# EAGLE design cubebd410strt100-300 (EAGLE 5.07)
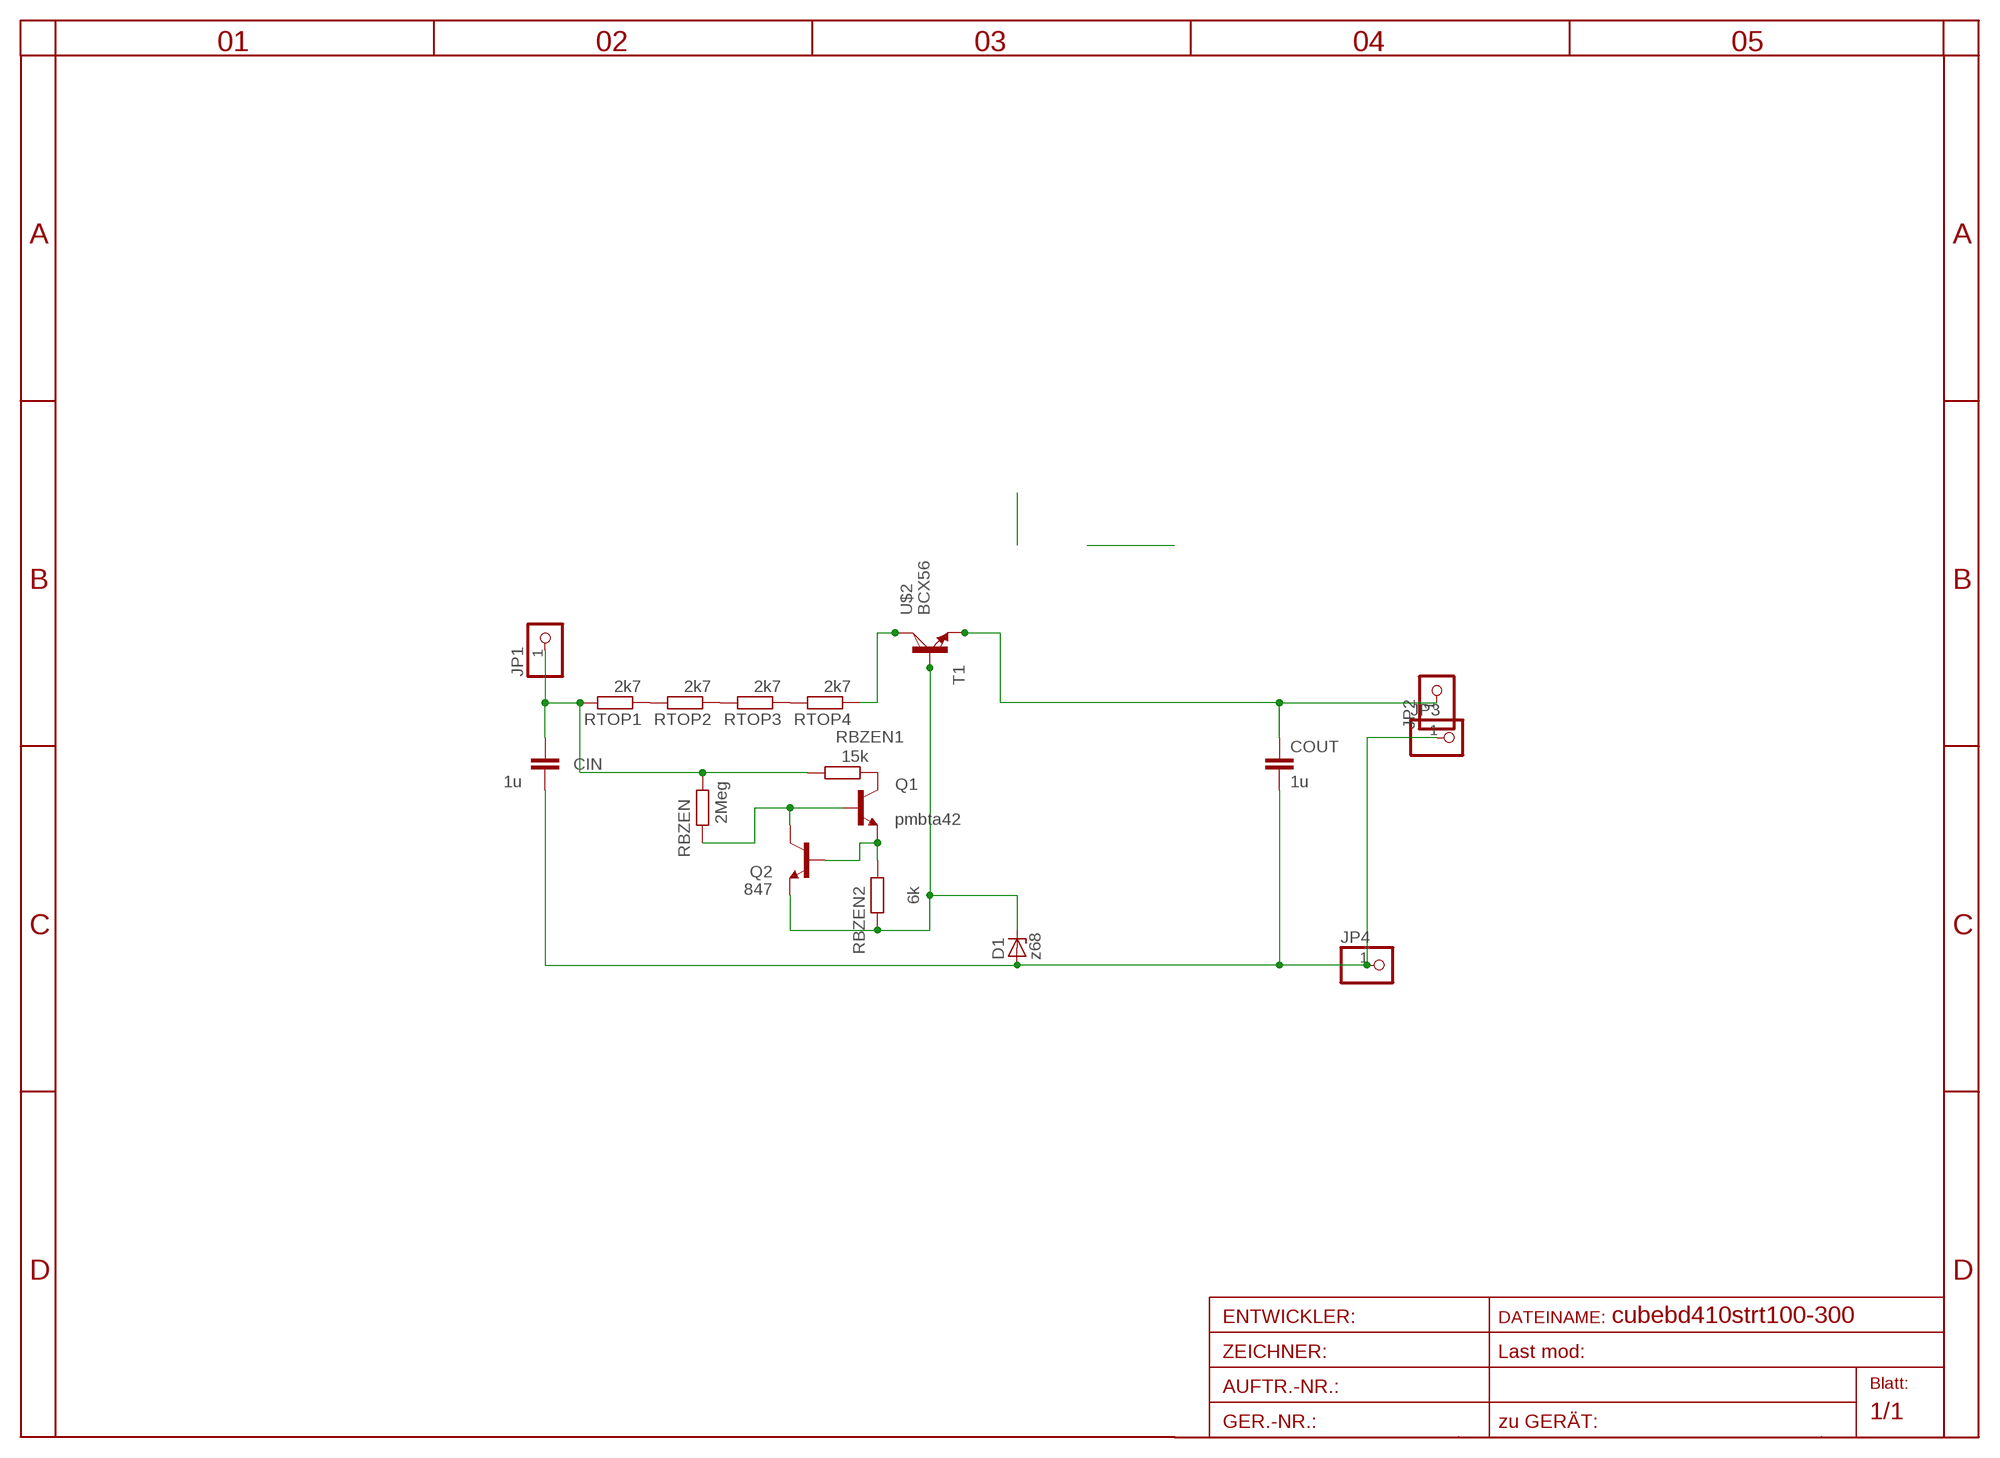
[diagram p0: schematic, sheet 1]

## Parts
CIN  1u  C-EU025-024X044  [C025-024X044]
COUT  1u  C-EU025_050-055X075  [C025_050-055X075]
D1  z68  ZENER-DIODESOD80C  [SOD80C]
JP1  PINHD-1X11X0.4  [1X01]
JP2  PINHD-1X11X0.4  [1X01]
JP3  PINHD-1X11X0.4  [1X01]
JP4  PINHD-1X11X0.4  [1X01]
Q1  pmbta42  BC847ASMD  [SOT23]
Q2  847  BC847ASMD  [SOT23]
RBZEN  2Meg  R-EU_0207/7  [0207/7]
RBZEN1  15k  R-EU_0207/7  [0207/7]
RBZEN2  6k  R-EU_0204/7  [0204/7]
RTOP1  2k7  R-EU_0204/2V  [0204V]
RTOP2  2k7  R-EU_0204/2V  [0204V]
RTOP3  2k7  R-EU_0204/2V  [0204V]
RTOP4  2k7  R-EU_0204/5  [0204/5]
T1  -NPN-TO126V  [TO126V]
U$2  BCX56  [SOT223]

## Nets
C: RTOP4.1 T1.2(C) U$2.2(C)
CB: Q1.1(B) Q2.3(C) RBZEN.2
DB: D1.C Q2.2(E) RBZEN2.2 T1.3(B) U$2.1(B)
EB: Q1.2(E) Q2.1(B) RBZEN2.1
GND: CIN.2 COUT.2 D1.A JP3.1 JP4.1
N$1: Q1.3(C) RBZEN1.1
N$2: RTOP1.1 RTOP2.2
N$7: RTOP2.1 RTOP3.2
N$8: RTOP3.1 RTOP4.2
OUT: COUT.1 JP2.1 T1.1(E) U$2.3(E)
VPLUS: CIN.1 JP1.1 RBZEN1.2 RBZEN.1 RTOP1.2

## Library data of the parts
CIN COUT = rcl:C-EU: CAPACITOR, European symbol
D1 = diode:ZENER-DIODE: Z-Diode
JP1-JP4 = pinhead:PINHD-1X1: PIN HEADER
Q1 Q2 = transistor-npn:BC847*: NPN Transistor
RBZEN RBZEN1 RBZEN2 RTOP1-RTOP4 = rcl:R-EU_: RESISTOR, European symbol
T1 = transistor:*-NPN-: NPN Transistror BF959 corrected 2008.03.06
U$2 = transistor-power:BCX56

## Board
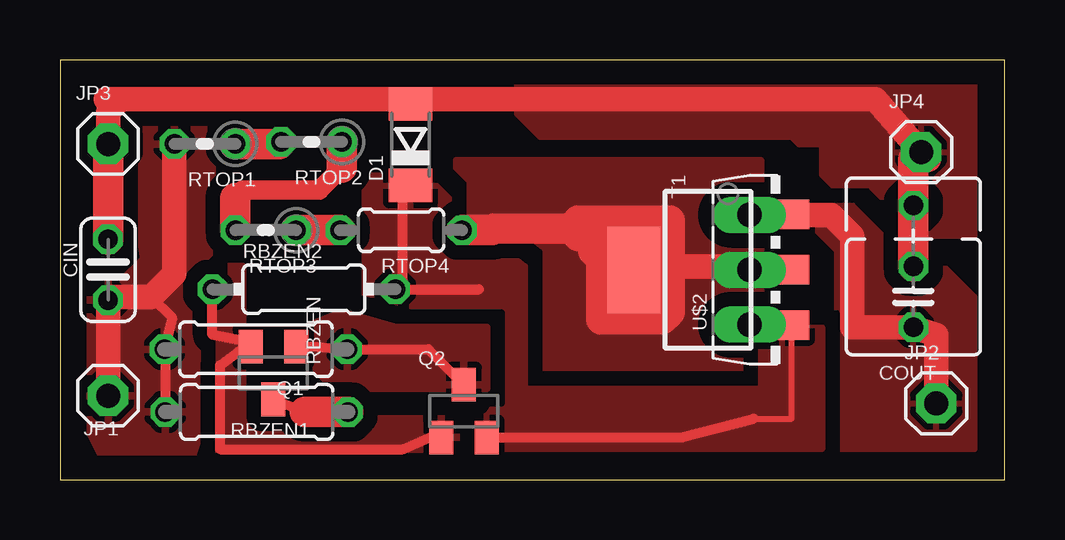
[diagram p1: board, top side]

Size 39.37 x 17.5 mm. Coordinates in mm from the lower left corner, seen from the top.
Outline: 0,0 39.37,0 39.37,17.5 0,17.5 0,0
Copper layers (1*16): Top 0.035mm / dielectric 1.5mm / Bottom 0.035mm
Design rules "default *": minimum track width 10mil, minimum drill 20mil, track to track 8mil, track to pad 8mil, pad to pad 8mil, via to via 8mil, smd to smd 8mil, copper to edge 40mil, drill to drill 8mil, minimum pad ring 1mil, minimum via ring 8mil, stop-mask expansion 4mil, vias tented up to drill 0mil, thermal gap 10mil

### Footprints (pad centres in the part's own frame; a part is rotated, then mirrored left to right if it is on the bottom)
C025-024X044 = drill 0.813 octagon: 1 -1.27,0; 2 1.27,0
C025_050-055X075 = drill 0.813 octagon: 1 -1.27,0; 2 1.27,0; 3 3.81,0
SOD80C = smd 1.4 x 1.8: A 1.7,0; C -1.7,0
1X01 = drill 1 pad 1.676 octagon: 1 0,0
SOT23 = smd 1 x 1.4: 1 -0.95,-1.1; 2 0.95,-1.1; 3 0,1.1
0207/7 = drill 0.813 octagon: 1 -3.81,0; 2 3.81,0
0204/7 = drill 0.813 octagon: 1 -3.81,0; 2 3.81,0
0204V = drill 0.813 octagon: 1 -1.27,0; 2 1.27,0
0204/5 = drill 0.813 octagon: 1 -2.54,0; 2 2.54,0
TO126V = drill 1.016 long: 1 -2.286,-1.27; 2 0,-1.27; 3 2.286,-1.27
SOT223 = smd 1.219 x 2.235: 1 -2.311,-3.099; 2 0,-3.099; 3 2.311,-3.099 | smd 3.6 x 2.2: 4 0,3.099

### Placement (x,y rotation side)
CIN  2,8.75 90 top
COUT  35.56,7.62 90 top
D1  14.61,13.97 90 top
JP1  2,3.5 0 top
JP2  36.51,3.17 0 top
JP3  2,14 0 top
JP4  35.88,13.65 0 top
Q1  8.89,4.45 180 top
Q2  16.83,2.86 0 top
RBZEN  8.16,5.44 0 top
RBZEN1  8.2,2.82 180 top
RBZEN2  10.16,7.94 0 top
RTOP1  6.03,14 180 top
RTOP2  10.48,14.08 180 top
RTOP3  8.57,10.4 180 top
RTOP4  14.21,10.4 180 top
T1  30,8.75 270 top
U$2  27,8.75 90 top

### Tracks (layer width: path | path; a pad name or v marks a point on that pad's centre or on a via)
C
  Top 0.305: 18.02,10.4 18.1,10.48
  Top 0.406: 27.68,8.89 T1.2
  Top 1.016: 20.95,10.48 25.4,8.89 27.68,8.89 | T1.2 U$2.2
  Top 1.27: 18.1,10.48 20.95,10.48 | RTOP4.1 18.02,10.4 | 21.59,10.16 21.59,10.79 25.4,10.79 25.4,6.99 25.08,6.67 22.54,6.67 22.54,9.21 22.23,9.53
  pour Top (isolate 0.61, rank 3, no thermals): 16.51,13.34 29.21,13.34 29.21,3.81 19.05,3.81 19.05,8.89 16.51,8.89
CB
  Top 0.406: Q1.1 10.49,5.54 RBZEN.2 15.35,5.44 Q2.3
  pour Top (isolate 0.61): 17.78,3.81 17.78,6.35 13.97,6.35 11.75,6.99 10.16,6.35 10.16,5.08 11.43,3.81
DB
  Top 0.254: 28.75,6.44 30.39,6.44 30.48,6.35 30.48,2.54 28.89,2.54
  Top 0.406: Q2.2 25.89,1.76 28.89,2.54 | 17.46,7.94 RBZEN2.2 14.29,8.26 14.29,12.27 D1.C
  Top 1.016: U$2.1 28.75,6.44 T1.3
  pour Top (isolate 0.61, rank 2): 12.7,12.7 15.24,12.7 17.78,10.16 19.37,8.89 19.37,3.81 29.21,3.81 29.21,6.35 31.75,6.35 31.75,1.27 17.78,1.27 17.78,6.35 13.65,6.35 12.7,7.62
EB
  Top 0.406: 7.94,5.71 Q1.2 | 7.94,5.71 6.35,6.04 RBZEN2.1 | Q2.1 15.41,1.76 14.29,1.27 6.67,1.27 6.67,4.76 7.94,5.71
  pour Top (isolate 0.61, rank 2): 7.62,8.89 7.62,2.54 16.51,2.54 16.51,1.27 6.35,1.27 6.35,8.89
GND
  Top 0.406: 13.65,15.88 D1.A | CIN.2 2.1,10.48
  Top 1.016: 2.54,15.88 1.91,15.88 | 2.54,15.88 13.65,15.88 33.97,15.88 JP4.1 36.2,13.34 35.56,13.34 | JP3.1 2,15.34 2.54,15.88
  Top 1.27: 35.56,13.34 COUT.2 | CIN.2 JP3.1
  pour Top (isolate 0.61, rank 4): 31.75,16.51 38.1,16.51 38.1,10.16 34.29,10.16 31.75,12.7 31.75,13.97 30.8,13.97 30.48,14.29 20,14.29 19.05,15.24 19.05,16.51
N$1
  Top 0.406: Q1.3 10.21,2.82
  Top 1.27: 10.21,2.82 RBZEN1.1
N$2
  Top 0.813: 9.12,14 RTOP2.2
  Top 1.27: RTOP1.1 9.12,14
N$7
  Top 0.813: 7.3,11.75 7.62,12.06 10.79,12.06 11.75,13.02
  Top 1.27: 11.75,13.02 RTOP2.1 | RTOP3.2 7.3,11.75
N$8
  Top 1.27: RTOP3.1 RTOP4.2
OUT
  Top 1.016: JP2.1 36.51,6.03 COUT.1 33.02,6.35 33.02,10.16 32.14,11.04 T1.1 28.75,11.06 U$2.3
  pour Top (isolate 0.61, rank 3): 30.48,11.43 33.02,11.43 35.56,8.89 36.83,8.89 38.1,7.62 38.1,1.27 32.38,1.27 32.38,9.53 31.75,10.16
VPLUS
  Top 0.406: RBZEN1.2 4.38,5.09 RBZEN.1 4.67,6.76 3.81,7.62
  Top 1.016: JP1.1 CIN.1 2.14,7.62 3.81,7.62 4.76,8.57 RTOP1.2
  pour Top (isolate 0.61): 2.54,15.24 6.35,15.24 6.35,9.53 5.71,8.89 5.71,1.59 5.4,0.64 1.91,0.64 1.27,1.91 1.27,8.26 2.54,8.26 3.49,9.21

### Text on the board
tStop: MICHAEL5.net
bStop: MICHAEL5.net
